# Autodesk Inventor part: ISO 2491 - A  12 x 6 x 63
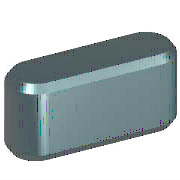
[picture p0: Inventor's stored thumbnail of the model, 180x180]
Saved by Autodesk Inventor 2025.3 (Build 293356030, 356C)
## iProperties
Created: 2024-01
Part Number: ISO 2491 - A  12 x 6 x 63
Material: Acciaio, Dolce
Description: Chiavette parallele sottili
Document SubType Name: Modeling
Standard: ISO 2491
Designer: R5800u
Standard Revision: First edition 1974-08-15
Standards Organization: ISO
Language: it-IT
Size Designation: A  12 x 6 x 63
Categories: <MemberInstance><Categories><Category DisplayName="Parti albero" InternalName="7f7aeb1f-a693-4053-b835-cee3144e0d98" Mnemonic="SHFT"><Category DisplayName="Chia
Density: 7.85 g/cm^3
Appearance: Semilucidato
IsCustomPart: 0
Author: R5800u
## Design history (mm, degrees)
workplane "Work Plane1"
workplane "Work Plane2"
sketch "Schizzo1"
  geometry: L1 (6, 6)-(57, 6); L2 (57, -6)-(6, -6); L3 (0, 9.4)-(0, -7.4) reference; L4 (-5, 0)-(30, 0) reference; L5 (63, 0)-(63, 7); A1 r 6 centre (6, 0) between (6, 6) and (6, -6); A2 r 6 centre (57, 0) between (57, -6) and (57, 6)
  constraints: 6 end point, 5 point on circle, 4 tangent, 3 point on line, 2 centre point, 1 horizontal, 1 parallel, 1 perpendicular
  dimensions: "d0" = 6 radius of A1 (= 0.5 x PB); "d13" = 6 radius of A2 (= 0.5 x PB); "d14" = 63 distance between parallel lines of L5 L3 (= NLG)
extrude "Corpo1" new body sketch "Schizzo1" taper "d3" = 0 deg; stored distance "d4" = 10
workplane "Work Plane3"
body "Solid1"
chamfer "Smusso1" distance "d8" = 0.6 (= PHH); stored, may be unused: second distance "d9" = 0.6 (= PHH), angle "d15" = 45 deg
other parameters: "d1" = -3.5 (= -PNT), "d2" = 2.5 (= PH - PNT), "NLG" = 63 [user parameter; used in 1 equation term], "PB" = 12 [user parameter; used in 2 equation terms], "PNT" = 3.5 [user parameter; used in 2 equation terms], "PH" = 6 [user parameter; used in 1 equation term], "PHH" = 0.6 [user parameter; used in 2 equation terms], "d10" = 0, "d16" = 0, "d17" = 0, "d18" = 0, "RR" = 0.25 [user parameter], "WDMIN" = 38 [user parameter], "WDMAX" = 44 [user parameter], "PLB1" = 63 [user parameter], "PLB2" = 63 [user parameter], "PUEB" = 2.8 [user parameter]
